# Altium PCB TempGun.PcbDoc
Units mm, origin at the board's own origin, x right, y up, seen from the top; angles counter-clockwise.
Board outline 71 x 30 mm, 3 copper layers (Top Layer, Mid-Layer 6, Bottom Layer); 43 components, 32 nets, 124 pads, 19 vias.
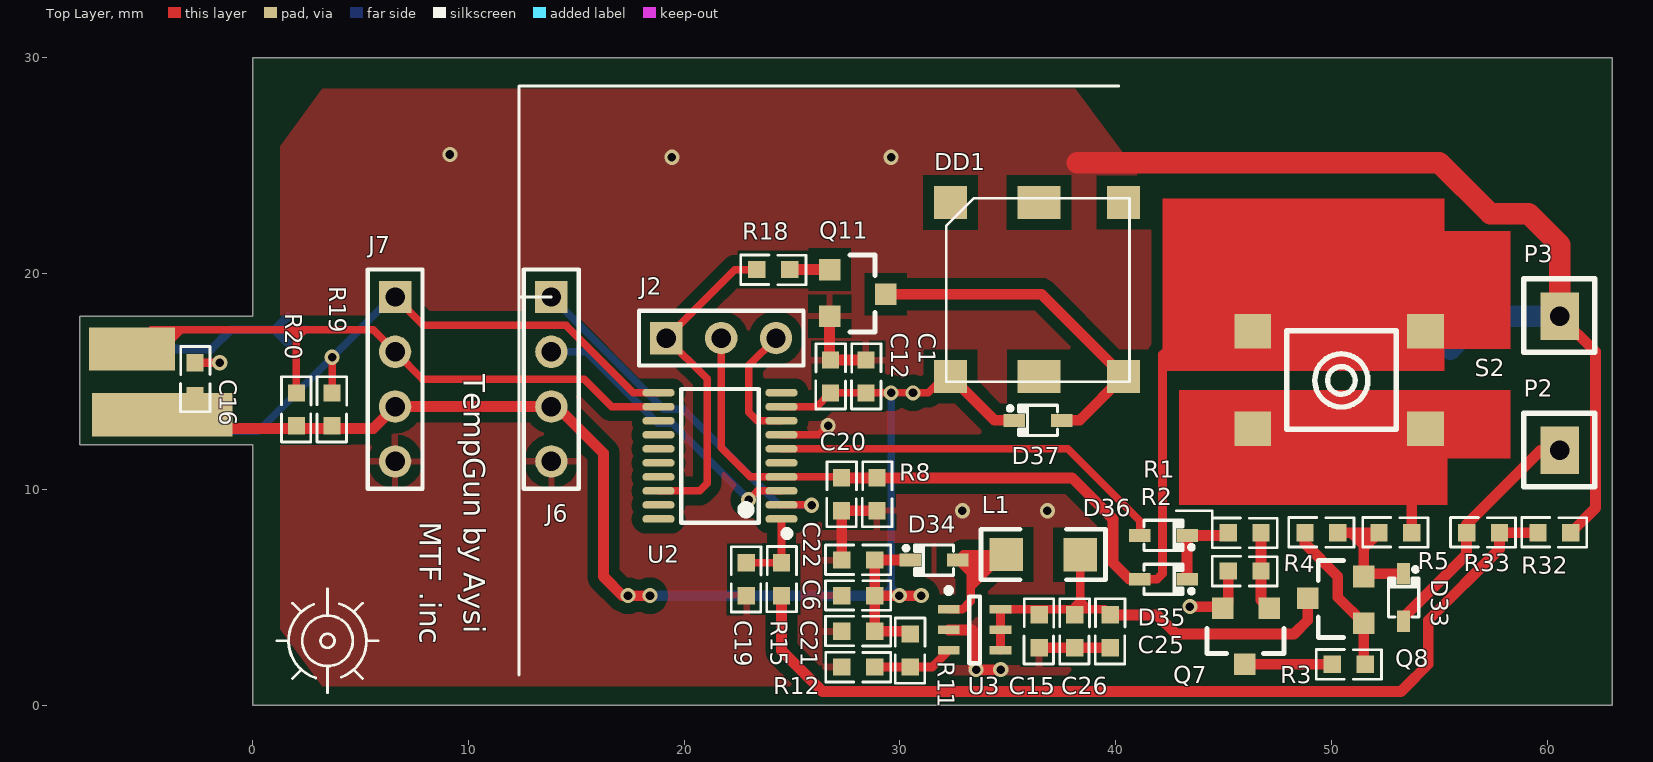
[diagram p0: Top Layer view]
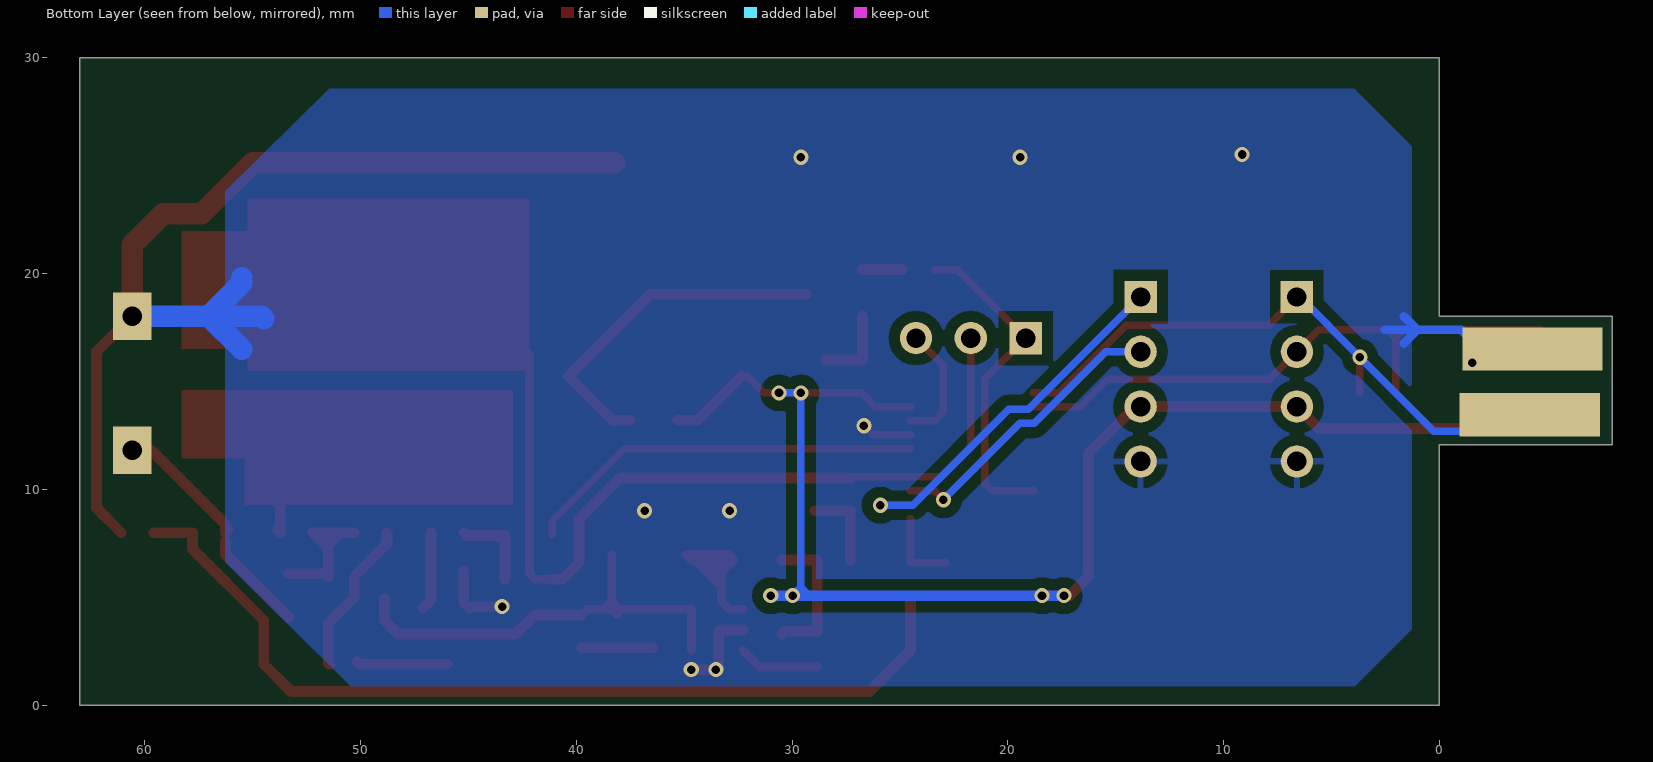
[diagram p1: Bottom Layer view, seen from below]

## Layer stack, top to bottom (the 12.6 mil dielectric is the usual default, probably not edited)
Top Layer: signal copper 0.0356
Dielectric: dielectric 0.32, FR-4, Dk 4.8
Mid-Layer 6: signal copper 0.0356
Dielectric: dielectric 0.32, FR-4, Dk 4.8
Bottom Layer: signal copper 0.0356

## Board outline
-8.001,12.065 -8.001,18.034 0,18.034 0,30 63,30 63,0 0,0 0,12.065

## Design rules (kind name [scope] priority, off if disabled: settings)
Clearance Clearance_1 [IsRegion] p1: gap=0.5
Clearance [All] p2: gap=0.3
PolygonConnect PolygonConnect_1 [IsVia] p1: connectstyle=Direct reliefconductorwidth=0.254 reliefentries=4 polygonreliefangle="90 Angle"
PolygonConnect [All] p2: connectstyle=Relief reliefconductorwidth=0.3 reliefentries=4 polygonreliefangle="90 Angle"
RoutingVias [All] p1: holewidth=0.4 width=0.7 viastyle="Through Hole" minholewidth=0.4 minwidth=0.7 maxholewidth=0.711 maxwidth=1.27
SilkToSilkClearance [All] p1: silktosilkclearance=0
SilkscreenOverComponentPads [IsPad] p1: minsilkscreentomaskgap=0
SolderMaskExpansion [All] p1: expansion=0.102
TestPointUsage [All] p1: valid=0 allowmultiple=FALSE
Testpoint [All] p1: side=3 testpointundercomponent=TRUE minsize=1.016 maxsize=2.54 preferedsize=1.524 minholesize=0 maxholesize=1.016 preferedholesize=0.813 testpointgrid=0.025 style=297 order=0123456789
Width [All] p1: maxlimit=2 minlimit=0.254 preferedwidth=0.3
22 further rules are at their usual default settings.

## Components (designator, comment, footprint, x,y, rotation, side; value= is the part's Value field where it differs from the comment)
C1 "106" 0603 28.429,14.477 r90 top
C6 "104" 0603 28.829,5.08 r180 top
C12 "104" 0603 26.778,14.477 r90 top
C15 "104" 0603 36.449,4.191 r270 top
C16 "104" 0603 -2.667,14.351 r90 top
C19 "104" 0603 22.879,6.603 r270 top
C20 "104" 0603 27.286,9.016 r90 top
C21 "106" 0603 28.829,3.429 r180 top
C22 "106" 0603 28.829,6.731 r180 top
C25 "106" 0603 39.751,4.191 r270 top
C26 "106" 0603 38.1,4.191 r270 top
D33 "1N5819" SOT-323 53.34,6.096 r270 top
D34 "1N5819" SOT-323 30.48,6.731 r0 top
D35 "1N4148" SOT-323 43.307,5.842 r180 top
D36 "1N4148" SOT-323 43.307,7.874 r180 top
D37 "1N4148" SOT-323 35.306,13.208 r0 top
DD1 "+5VDD" 8530 40.64,23.495 r270 top
J2 "CON3" HDR1X3 19.177,17.018 r0 top
J6 "OLED" HDR1X4 13.843,18.923 r270 top locked
J7 "MLX90615" HDR1X4 6.604,18.923 r270 top
L1 "2.2uH" 1206 38.354,6.985 r180 top
P2 "CN1" 1PIN 60.579,11.811 r0 top
P3 "CN1" 1PIN 60.579,18.034 r0 top
Q7 "S8050" SOT-23-3 45.974,1.905 r90 top
Q8 "AO3401" SOT-23-3 48.895,4.953 r0 top
Q11 "S8050" SOT-23-3 29.337,19.05 r180 top
R1 "4.7K" 0603 45.212,8.001 r0 top
R2 "10K" 0603 45.212,6.223 r0 top
R3 "4.7K" 0603 50.038,1.905 r0 top
R4 "10K" 0603 50.292,8.001 r180 top
R5 "1K" 0603 53.721,8.001 r180 top
R8 "10K" 0603 28.937,9.016 r90 top
R11 "75K" 0603 30.48,3.302 r270 top
R12 "20K" 0603 27.305,1.778 r0 top
R15 "1K" 0603 24.511,5.08 r90 top
R18 "4.7K" 0603 23.368,20.193 r0 top
R19 "10K" 0603 3.683,14.478 r270 top
R20 "10K" 0603 2.032,14.478 r270 top
R32 "10K" 0603 61.087,8.001 r180 top
R33 "10K" 0603 57.785,8.001 r180 top
S2 "SW-PB" SW-4-SMD 54.356,12.827 r90 top
U2 "N76E003" TSSOP-20 24.511,8.636 r90 top
U3 "XR1151" SOT-23-6 32.258,4.445 r0 top

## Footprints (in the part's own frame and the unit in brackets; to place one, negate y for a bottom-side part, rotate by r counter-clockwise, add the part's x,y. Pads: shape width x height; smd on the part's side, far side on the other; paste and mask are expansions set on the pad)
1PIN [mm]
  rect 1.8x2.2 hole 0.9: 1(0,0)
  silkscreen extent -1.68,-1.68 1.63,1.72
0603 [mm]
  rect 0.8x0.8 smd: 1(0,0) 2(1.524,0)
  silkscreen extent -0.74,-0.7 2.27,0.68, body extent 0,-0.4 1.53,0.4, height 1
1206 [mm]
  rect 1.55x1.55 smd: 1(0,0) 2(3.43,-0.004)
  silkscreen extent -1.17,-1.17 4.6,1.17, body extent 0,-0.87 3.45,0.87, height 2
8530 [mm]
  rect 1.524x1.524 smd: 0(0.2,-0.275) 0(0.2,-8.3) 1(8.25,-8.3) 2(8.25,-0.275)
  rect 1.524x2 smd: 0(0.2,-4.2) 0(8.25,-4.2)
  silkscreen extent 0,-8.5 8.5,0
HDR1X3 [mm] "Connector; Header; 3 Position"
  rect 1.5x1.5 hole 0.9: 1(0,0)
  round 1.5 hole 0.9: 2(2.54,0) 3(5.08,0)
  silkscreen extent -1.27,-1.27 6.35,1.27
HDR1X4 [mm] "Connector; Header; 4 Position"
  rect 1.5x1.5 hole 0.9: 1(0,0)
  round 1.5 hole 0.9: 2(2.54,0) 3(5.08,0) 4(7.62,0)
  silkscreen extent -1.27,-1.27 8.89,1.27
SOT-23-3 [mm]
  rect 1x1 smd: 1(0,0) 2(2.598,-1.143) 3(2.598,1.016)
  silkscreen extent 0.49,-1.82 1.66,1.75, body extent 0.48,-1.8 2.07,1.75, height 1
SOT-23-6 [mm]
  rect 1x0.4 smd: 1(0,0) 2(0,-0.95) 3(0,-1.9) 4(2.4,-1.9) 5(2.4,-0.95) 6(2.4,0)
  silkscreen extent -0.12,-2.5 1.45,1
SOT-323 [mm]
  rect 1x0.6 smd: 1(2.2,0) 2(0,0)
  silkscreen extent -0.3,-0.7 2,0.7
SW-4-SMD [mm]
  rect 1.6x1.7 smd: 1(0,8) 1(0,0) 2(4.5,8) 2(4.5,0)
  silkscreen extent -0.04,1.35 4.53,6.43
TSSOP-20 [mm]
  oval 0.35x1.5 smd: 1(0,0) 2(0.65,0) 3(1.3,0) 4(1.95,0) 5(2.6,0) 6(3.25,0) 7(3.9,0) 8(4.55,0) 9(5.2,0) 10(5.85,0) 11(5.85,5.7) 12(5.2,5.7) 13(4.55,5.7) 14(3.9,5.7) 15(3.25,5.7) 16(2.6,5.7) 17(1.95,5.7) 18(1.3,5.7) 19(0.65,5.7) 20(0,5.7)
  silkscreen extent -0.82,-0.4 6.02,4.65, body extent -0.38,0.55 6.22,5.15, height 1

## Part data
C1 C12: library part CAP
C6: library part CAP, "Capacitor"
C15 C16 C19 C20 C21 C22 C25 C26: library part CAP_W
D33 D34 D35 D36 D37: library part Diode, "Default Diode"
DD1: library part Pro58.tmp_UnNamed_18
J2: library part "Header 3", "Header, 3-Pin"
J6 J7: library part "Header 4", "Header, 4-Pin"
L1: library part INDUCTOR1_W
Q7 Q11: library part NPN, "NPN Bipolar Transistor"
Q8: library part MOSFET-P, "P-Channel MOSFET"
R1 R2 R3 R4 R5 R8 R11 R12 R15 R18 R19 R20 R32 R33: library part Res2, "Resistor"
S2: "Switch"

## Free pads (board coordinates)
  rect 6.5x2 smd: 0(-4.191,13.462)
  rect 4x2 smd: 1(-5.588,16.51)
  rect 6.5x2 smd far side: 2(-4.318,16.51) 3(-4.191,13.462)

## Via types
v1: diameter 0.7, hole 0.4, Top Layer to Bottom Layer, tented both sides, 19 vias

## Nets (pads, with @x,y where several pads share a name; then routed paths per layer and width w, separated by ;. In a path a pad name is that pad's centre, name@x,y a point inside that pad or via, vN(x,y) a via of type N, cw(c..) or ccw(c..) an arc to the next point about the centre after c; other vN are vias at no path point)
+3.3V: C1.1 C6.1 C12.1 C16.1 C21.1 C22.1 D34.2 D37.2 DD1.1 J6.3 J7.3 pad.0 R11.1 R19.2 R20.2 U2.9 | length 74.9
  Top Layer w0.35: U2.9 26.137,13.836 C12.1 C1.1 v1(29.591,14.478) v1(30.607,14.478) 31.319,14.478 DD1.1@32.086,15.245
  Top Layer w0.5: pad.0@-1.016,12.827 1.143,12.827 5.588,12.827 J7.3 J6.3 14.097,13.843 16.256,11.684 16.256,5.969 17.145,5.08 v1(18.415,5.08) v1(17.399,5.08) ; C6.1 v1(29.972,5.08) v1(30.988,5.08) ; R11.1 30.353,3.429 C21.1 C22.1 D34.2 ; DD1.1 34.377,13.208 D37.2
  Bottom Layer w0.35: 29.21,5.08 29.591,5.461 ; 29.591,5.08 29.591,5.588 ; v1(29.972,5.08) 29.591,5.461 ; v1(30.607,14.478) v1(29.591,14.478) 29.591,5.588 ; 29.591,5.461 29.591,5.588
  Bottom Layer w0.5: v1(18.415,5.08) v1(17.399,5.08) 27.432,5.08 v1(29.972,5.08) v1(30.988,5.08)
A: U2.20
B: U2.19
BAT+: D33.1 P2.1 R33.2 | length 11.4
  Top Layer w0.5: D33.1@53.34,4.064 56.261,6.985 R33.2@56.261,7.62 ; R33.2@56.134,8.128 R33.2 56.261,8.382 59.69,11.811 P2.1@60.96,11.811
C: U2.17
D: U2.16
DIG1: J6.1 U2.2 | length 17.5
  Top Layer w0.35: U2.2 25.893,9.286 v1(25.908,9.271)
  Bottom Layer w0.35: J6.1 19.05,13.716 19.963,13.716 24.408,9.271 v1(25.908,9.271)
DIG2: J6.2 U2.3 | length 13.7
  Top Layer w0.35: v1(22.987,9.525) 23.398,9.936 U2.3
  Bottom Layer w0.35: J6.2 15.464,16.383 18.781,13.066 19.446,13.066 v1(22.987,9.525)
DIG3: U2.5
DIG4: J2.3 U2.8 | length 5.6
  Top Layer w0.35: J2.3 22.987,15.748 22.987,13.589 23.39,13.186 U2.8
E: U2.15
G: U2.13
GND: C1.2 C6.2 C12.2 C15.2 C16.2 C19.2 C20.1 C21.2 C22.2 C25.2 C26.2 J6.4 J7.4 P3.1 pad.2 Q7.3 Q11.3 R2.1 R8.1 R12.1 R32.1 U2.7 U3.2 | length 80.2
  Top Layer w0.35: U2.7 26.252,12.536 v1(26.67,12.954) ; C12.2@26.739,16.041 C12.2
  Top Layer w0.4: C16.2 v1(-1.524,15.875)
  Top Layer w0.5: C12.2@26.739,16.041 Q11.3 ; C12.2 C1.2 ; C22.2 27.305,8.998 C20.1 R8.1 ; U3.2 33.335,3.495 33.401,3.429 33.401,1.778 v1(33.528,1.651) v1(34.671,1.651) ; C15.2 C25.2 ; v1(43.434,4.572) 44.889,4.572 Q7.3 45.212,4.757 R2.1 ; P3.1 62.23,16.383 62.23,9.144 R32.1
  Top Layer w1: 38.227,25.146 54.991,25.146 57.366,22.771 59.144,22.771 59.182,22.733 60.579,21.336 P3.1
  Bottom Layer w0.4: pad.2@-4.445,16.51 -1.905,16.51 -1.016,17.399 1.016,17.399 ; 1.651,16.764 1.016,17.399 ; 1.651,18.034 1.016,17.399 ; 2.54,17.399 1.016,17.399
  Bottom Layer w1: 54.483,17.907 54.61,18.034 57.023,18.034 ; 55.499,16.51 57.023,18.034 ; 55.499,19.812 55.499,19.558 57.023,18.034 ; P3.1 57.023,18.034
  other v1: 32.893,9.017 36.83,9.017 19.431,25.4 29.591,25.4 9.144,25.527
H: U2.10
ICPCK: J2.1 R18.1 U2.18 | length 15.5
  Top Layer w0.35: U2.18 20.574,9.936 ; 20.656,9.936 20.574,9.936 ; R18.1 22.352,20.193 J2.1 21.067,15.128 21.067,10.287 20.716,9.936 20.574,9.936
NetC19_1: C19.1 R15.2 U2.1 | length 3.7
  Top Layer w0.35: C19.1 R15.2 U2.1
NetD33_2: D33.2 Q8.3 R4.1 R5.2 | length 7.8
  Top Layer w0.5: R4.1 51.562,8.001 ; 50.927,8.001 51.493,7.435 51.493,7.297 ; D33.2 51.62,6.096 Q8.3 51.493,7.297 ; 51.493,7.297 51.562,7.366 51.562,8.001 ; 51.493,7.297 R5.2 51.562,8.001
NetD34_1: D34.1 L1.2 U3.1 | length 12.9
  Top Layer w0.4: U3.1 32.893,4.445 33.274,4.826 33.274,5.461 ; 33.274,5.756 33.274,5.715 ; 33.655,6.137 33.274,6.137 ; D34.1 32.938,6.989 L1.2 ; D34.1 33.041,6.371 ; D34.1 L1.2@34.666,6.731 ; 33.041,6.371 33.803,6.371 34.163,6.731 L1.2@34.666,6.731 ; 33.041,6.371 33.274,6.137 ; 33.274,5.461 34.802,6.989 L1.2 ; 33.274,5.461 33.274,5.715 ; 33.274,5.715 33.274,6.137 ; L1.2@34.666,6.731 L1.2 ; L1.2@34.666,6.731 L1.2
NetD35_2: D35.2 D36.2 R1.1 | length 4
  Top Layer w0.5: D35.2 D36.2 45.085,7.874 R1.1
NetD37_1: D37.1 DD1.2 Q11.1 | length 16.3
  Top Layer w0.5: Q11.1 36.56,19.05 DD1.2 38.328,13.208 D37.1
NetQ7_1: Q7.1 R3.1 | length 4.2
  Top Layer w0.5: Q7.1 R3.1 R3.1@50.165,2.032
NetQ7_2: Q7.2 R1.2 R2.2 | length 3.7
  Top Layer w0.5: R1.2 R2.2 46.736,4.884 Q7.2
NetQ8_2: Q8.2 R3.2 R4.2 | length 7.2
  Top Layer w0.5: R4.2 48.768,7.493 50.292,5.969 50.292,5.011 Q8.2 51.493,1.963 R3.2@51.435,1.905
NetQ11_2: Q11.2 R18.2 | length 1.8
  Top Layer w0.5: R18.2 Q11.2
NetR5_1: R5.1 S2.1 | length 13.3
  Top Layer w0.5: S2.1@46.356,12.827 54.356,12.827 53.721,12.192 R5.1 R5.1@53.848,8.128
NetR11_2: R11.2 R12.2 U3.3 | length 3.7
  Top Layer w0.4: R12.2 31.491,1.778 U3.3
NetR15_1: R15.1 R32.2 R33.1 | length 43.1
  Top Layer w0.5: R15.1 24.511,2.54 26.416,0.635 53.213,0.635 53.34,0.762 54.483,1.905 54.483,3.937 57.785,7.239 R33.1 R32.2
P1.7: D36.1 U2.6 | length 18.7
  Top Layer w0.35: U2.6 37.771,11.886 41.107,8.55 D36.1
"POWER KEY": C20.2 D35.1 J2.2 R8.2 S2.2 U2.4 | length 52.2
  Top Layer w0.35: J2.2 21.717,11.938 23.069,10.586 U2.4 27.24,10.586 C20.2
  Top Layer w0.4: D35.1 41.91,5.842 42.164,6.096 42.164,16.256 43.235,17.327
  Top Layer w0.5: C20.2 R8.2 35.688,10.54 37.212,10.54 37.974,10.54 39.878,8.636 39.878,6.604 40.64,5.842 D35.1 D35.1@41.129,5.82 ; 43.235,17.327 S2.2@54.356,17.327
SCL: J7.2 pad.1 R20.1 U2.12 | length 33.4
  Top Layer w0.35: 1.397,17.399 1.651,17.399 2.032,17.018 ; R20.1 2.032,16.764 ; 2.032,17.399 2.032,17.018 ; 2.413,17.399 2.032,17.018 ; U2.12 16.644,13.836 15.367,15.113 7.874,15.113 J7.2 5.588,17.399 -3.302,17.399 ; -3.302,17.399 -4.191,16.51 pad.1 -4.699,17.399 -3.302,17.399 ; 2.032,16.764 2.032,17.018 ; 2.032,16.764 2.032,17.018
SDA: J7.1 pad.3 R19.1 U2.11 | length 29.8
  Top Layer w0.35: R19.1 v1(3.683,16.129) ; J7.1 7.919,17.608 14.523,17.608 17.645,14.486 U2.11
  Bottom Layer w0.35: pad.3 -1.905,13.462 -1.143,12.7 0.254,12.7 ; 0.127,12.7 0.254,12.7 ; J7.1@6.604,18.669 J7.1 6.477,18.923 v1(3.683,16.129) 0.254,12.7
VCC: C15.1 C25.1 C26.1 L1.1 Q8.1 U3.4 U3.5 U3.6 | length 22.3
  Top Layer w0.4: U3.4 U3.6 39.497,4.445 C25.1 ; L1.1 38.354,4.826 ; 38.989,4.445 38.735,4.445 38.354,4.826 ; 38.354,4.826 38.1,4.572 C26.1 38.354,4.445 38.354,4.826
  Top Layer w0.5: C25.1 41.91,4.191 42.799,3.302 48.26,3.302 48.895,3.937 Q8.1
pads on no net: DD1.0 U2.14

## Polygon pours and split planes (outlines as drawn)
GND on Top Layer "Bottom Layer-No Net" (solid, remove dead copper, pour order 1000): 1.27,25.908 3.229,28.575 38.128,28.575 41.656,23.815 41.656,6.652 37.385,0.889 3.22,0.889 1.27,3.52
GND on Bottom Layer "Bottom Layer-No Net" (solid, remove dead copper, pour order 1001): 1.27,25.908 3.937,28.575 51.457,28.575 56.261,23.815 56.261,6.652 50.446,0.889 3.925,0.889 1.27,3.52

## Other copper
Top Layer:
  rectangle net NetR5_1: 55.118,11.43 58.293,14.605
  rectangle net NetR5_1: 42.926,9.271 55.372,14.605
  rectangle net "POWER KEY": 55.118,16.51 58.293,21.971
  rectangle net "POWER KEY": 42.164,15.494 55.245,23.495

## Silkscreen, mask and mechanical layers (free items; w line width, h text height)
Top Overlay:
  circle w0.127: c3.471,2.989 r0.324
  circle w0.127: c3.471,2.989 r1.171
  lines w0.127: 1.122,2.989 1.63,2.989 ; 1.852,1.243 2.265,1.656 ; 1.852,4.735 2.265,4.323 ; 2.837,4.679 ccw(c3.471,2.989) 2.921,1.27 ; 3.471,0.576 3.471,1.818 ; 3.471,4.16 3.471,5.402 ; 4.021,4.708 cw(c3.471,2.989) 4.105,1.299 ; 4.678,1.656 5.09,1.243 ; 4.678,4.323 5.09,4.735 ; 5.313,2.989 5.821,2.989 ; 12.343,1.402 12.343,28.702 40.143,28.702 ; 12.343,18.923 13.843,18.923 ; 42.799,9.017 44.467,9.017 44.467,8.653
  text "TempGun by Aysi" at 9.779,15.346 h1 r270
  text "MTF .inc" at 7.747,8.509 h1 r270
Top Solder:
  rectangle: 42.164,15.494 55.245,23.495
  rectangle: 54.356,16.51 58.293,21.971
  rectangle: 55.118,11.43 58.293,14.605
  rectangle: 42.926,9.271 55.372,14.605
Mechanical 1:
  circle w0.127: c0,13.97 r0.35
  circle w0.127: c0,16.51 r0.35
  circle w0.127: c0,15.24 r0.35
  circle w0.127: c5,23.5 r1.25
  circle w0.127: c60.5,3.5 r1.25
  circle w0.127: c60.5,26.5 r1.25
  circle w0.127: c58.005,3.5 r2
  circle w0.127: c58.005,26.5 r2
  circle w0.127: c5,6.5 r1.25
  lines w0.127: -8.001,12.065 -3.048,12.065 0,12.065 0,0 63,0 63,30 0,30 0,18.034 -3.048,18.034 -8.001,18.034 -8.001,12.065
Mechanical 13:
  circle w0.127: c50.5,15 r1.461
  lines w0.127: 36.25,15 44.25,15 50.5,15 60.5,15 ; 5,6.5 60.5,6.5 60.5,23.5 5,23.5 5,6.5 ; 16.25,4 36.25,4 36.25,26 16.25,26 16.25,4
